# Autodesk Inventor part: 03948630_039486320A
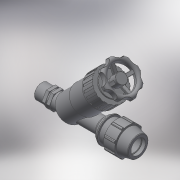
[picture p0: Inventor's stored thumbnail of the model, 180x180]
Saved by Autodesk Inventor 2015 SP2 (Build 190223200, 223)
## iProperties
Created: 2017-02
Part Number: 03948630_039486320A
Material: Generic
Description: PLASSON ANGLE SEAT VALVE 63-2"
Document SubType Name: Modeling
Designer: KIM
Mass: 2680.84 g
Surface Area: 2686.58 cm^2
Volume: 2680.84 cm^3
Density: 1 g/cm^3
Appearance: Default
Author: KIM
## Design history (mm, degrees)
derived "03048-03948.ipt"
feature "Solid1::03048-03948.ipt"
tag "TaggingFeature1"
body "Solid1"
other parameters: "d2" = 63, "d4" = 14.16667, "d5" = 34, "d7" = 113, "d11" = 4.85714, "d13" = 120 deg, "d14" = 88.2, "d15" = 12 deg, "d16" = 98.31, "d18" = 3.15, "d19" = 35 deg, "d20" = 17.5 deg, "d21" = 105.09, "d23" = 0, "d25" = 360 deg, "d27" = 2.26, "d33" = 1.26, "d42" = 40.8, "d43" = 3.39, "d46" = 1.89, "d67" = 84.75, "d96" = 8.5, "d159" = 2, "d165" = 221.4, "d167" = 132.84, "d168" = 39.852, "d169" = 39.852, "d170" = 90 deg, "d171" = 70 deg, "d172" = 31.8816, "d173" = 92.988, "d174" = 92.988, "d175" = 119.556, "d176" = 135 deg, "d177" = 106.272, "d178" = 99.63, "d179" = 55.35, "d180" = 221.4, "d182" = 31.8816, "d183" = 87.6744, "d190" = 45 deg, "d191" = 68, "d192" = 4.92, "d193" = 4.52, "d194" = 2.26, "d195" = 115.96932, "d198" = 0, "d199" = 49.815, "d200" = 113, "d204" = 360 deg, "d209" = 0, "d213" = 6.642, "d216" = 360 deg, "d220" = 112.914, "d221" = 3.39, "d222" = 3.39, "d223" = 6.78, "d227" = 3.39, "d229" = 0, "d230" = 1.23, "d232" = 360 deg, "d234" = 1.23, "d235" = 1.23, "d237" = 360 deg, "d239" = 1.968, "d241" = 1.23, "d249" = 59.614, "d250" = 45 deg, "d251" = 50.4, "d253" = 26, "d254" = 8.66667, "d255" = 4.33333, "d256" = 66, "d258" = 0, "d260" = 0, "d261" = 1.19228, "d265" = 0, "d266" = 246, "d_" = 63, "E_" = 113, "A_" = 246, "d224" = 113, "G_" = 59.614, "l_2" = 26, "d202" = 119.556, "d214" = 132.84, "d218" = 132.84, "d225" = 132.84, "d226" = 92.988
